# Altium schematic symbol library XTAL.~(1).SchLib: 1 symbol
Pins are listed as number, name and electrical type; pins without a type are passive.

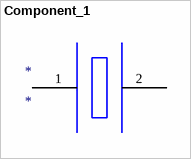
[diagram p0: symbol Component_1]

## Component_1
designator *
pins: 1 X1, 2 X2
